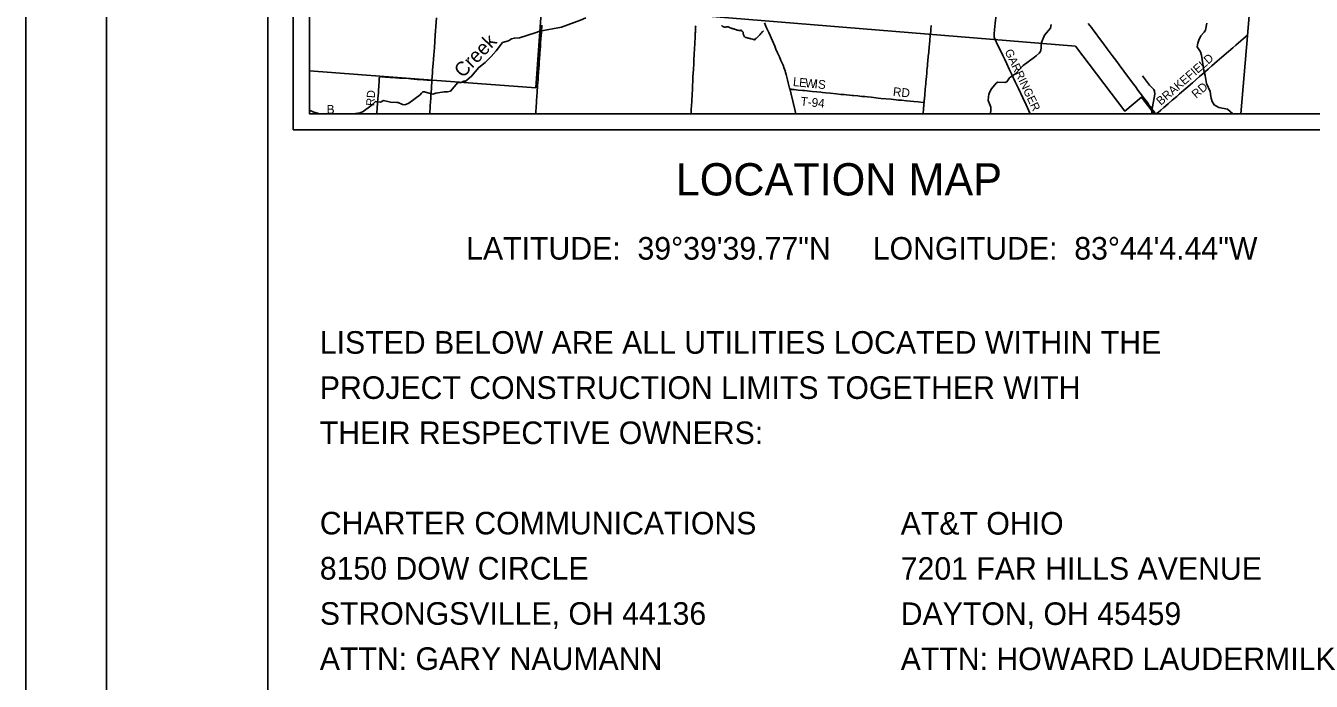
# Model space of a CAD drawing. Extents: x -13.9 to 69.1, y -25.2 to 26.1.
# Drawn here: x 0 to 7.96, y 10.9 to 14.96 of the extents above; entities that cross this region are included whole.
import ezdxf

# ---------------------------------------------------------------- set-up
doc = ezdxf.new("R2010")
doc.units = 0
for name, color, linetype in [('GM_X_County_Road', 7, 'Continuous'), ('GM_X_County_Road_Text', 7, 'Continuous'), ('GM_X_Minor_River', 7, 'Continuous'), ('GM_X_Minor_River_Text', 7, 'Continuous'), ('GM_X_State_Route', 7, 'Continuous'), ('GM_X_Township', 7, 'Continuous'), ('GM_X_Township_Road', 7, 'Continuous'), ('GM_X_Township_Road_Text', 7, 'Continuous'), ('SH_Border', 7, 'Continuous'), ('SH_Cut_Line', 7, 'Continuous'), ('SH_Data', 7, 'Continuous'), ('SH_Text', 7, 'Continuous')]:
    doc.layers.add(name, color=color, linetype=linetype)

msp = doc.modelspace()

# ---------------------------------------------------------------- linework, layer by layer
at = {"layer": 'GM_X_County_Road'}
for points in [[(5.9984, 14.8932), (5.9981, 14.8949), (5.9976, 14.8983), (5.9975, 14.9042), (5.9979, 14.9107), (6.0005, 14.9343), (6.0055, 14.9767), (6.0095, 15.0122), (6.0141, 15.0529), (6.0187, 15.0924), (6.0245, 15.1462), (6.03, 15.194), (6.0338, 15.224)], [(2.5162, 14.6214), (2.5164, 14.6263), (2.5173, 14.6411), (2.5177, 14.6476), (2.5179, 14.6506), (2.5187, 14.6636), (2.5195, 14.6754), (2.5204, 14.6879), (2.5234, 14.727), (2.5252, 14.7501), (2.5277, 14.7827), (2.529, 14.7987), (2.5312, 14.8272), (2.5338, 14.8597), (2.5371, 14.903), (2.5389, 14.9261), (2.5411, 14.9564), (2.5452, 15.0097)], [(6.5812, 14.9747), (6.6003, 14.9492), (6.6153, 14.9294), (6.6294, 14.9102), (6.6448, 14.8893), (6.6712, 14.854), (6.6979, 14.8177), (6.7298, 14.7751), (6.7573, 14.7385), (6.7733, 14.7173), (6.8023, 14.6783), (6.8244, 14.6485), (6.8327, 14.6374), (6.8617, 14.5984), (6.8735, 14.5826), (6.889, 14.5618), (6.9177, 14.5235)], [(3.1701, 14.5785), (3.1709, 14.5907), (3.1719, 14.6055), (3.1734, 14.6275), (3.1744, 14.6411), (3.177, 14.6761), (3.18, 14.7164), (3.1804, 14.7218), (3.1811, 14.733), (3.1847, 14.7846), (3.1849, 14.787), (3.1848, 14.7876), (3.1849, 14.7894), (3.1879, 14.8315), (3.1881, 14.8344), (3.1893, 14.851), (3.1915, 14.8836), (3.1924, 14.8979), (3.194, 14.9192), (3.1949, 14.9335), (3.1962, 14.9542), (3.1968, 14.9637)], [(4.1212, 14.4145), (4.1217, 14.4244), (4.1226, 14.4411), (4.1252, 14.491), (4.1279, 14.5384), (4.129, 14.5634), (4.1305, 14.5967), (4.1312, 14.6091), (4.133, 14.6436), (4.1354, 14.6887), (4.1373, 14.7255), (4.1385, 14.7486), (4.1391, 14.7599), (4.1399, 14.7736), (4.1406, 14.7866), (4.1423, 14.8151), (4.1428, 14.824), (4.1439, 14.8436), (4.1452, 14.8668), (4.1456, 14.8751), (4.1462, 14.8876), (4.1475, 14.9143), (4.1478, 14.9214), (4.1483, 14.9333), (4.1484, 14.9357), (4.1487, 14.9434), (4.1492, 14.9529), (4.1496, 14.9606)], [(6.2219, 14.4145), (6.1961, 14.47), (6.176, 14.5131), (6.1492, 14.5704), (6.1295, 14.6124), (6.1061, 14.6617), (6.0923, 14.6908), (6.0769, 14.7231), (6.064, 14.7501), (6.052, 14.7749), (6.029, 14.8236), (6.016, 14.8506), (6.0088, 14.866), (6.0037, 14.8771), (6.0015, 14.8823), (6.0003, 14.8856), (5.9993, 14.8888), (5.9986, 14.892), (5.9984, 14.8932)], [(2.5023, 14.4145), (2.5027, 14.4199), (2.5048, 14.4566), (2.5058, 14.4703), (2.5064, 14.4822), (2.5089, 14.5156), (2.5101, 14.5314), (2.5107, 14.5397), (2.5109, 14.5427), (2.5118, 14.5551), (2.5125, 14.5646), (2.5136, 14.5824), (2.5143, 14.5925), (2.515, 14.602), (2.5158, 14.6144), (2.5161, 14.6204), (2.5162, 14.6214)], [(3.1583, 14.4145), (3.1586, 14.4188), (3.1588, 14.4211), (3.1598, 14.4318), (3.1611, 14.449), (3.1617, 14.4579), (3.1635, 14.484), (3.1642, 14.4946), (3.1647, 14.5023), (3.1656, 14.5154), (3.1667, 14.5302), (3.1675, 14.5421), (3.1685, 14.5569), (3.1701, 14.5785)], [(6.9177, 14.5235), (6.9299, 14.5071), (6.9475, 14.4834), (6.9568, 14.4708), (6.9658, 14.4588), (6.9738, 14.4481), (6.9905, 14.4256)], [(6.9905, 14.4256), (6.9945, 14.4202), (6.9988, 14.4145)]]:
    msp.add_lwpolyline(points, dxfattribs=at)
at = {"layer": 'GM_X_Minor_River'}
for points in [[(3.1838, 14.9264), (3.3179, 14.9511), (3.4361, 14.9956), (3.4696, 15.0093)], [(7.3159, 14.9759), (7.3067, 14.932), (7.2998, 14.9201), (7.2789, 14.897), (7.2658, 14.8717), (7.2592, 14.8514), (7.2574, 14.8424), (7.2559, 14.8289), (7.2759, 14.7981), (7.2828, 14.7769), (7.2965, 14.6828), (7.3046, 14.6525), (7.3126, 14.6029), (7.3358, 14.5517), (7.3413, 14.5221), (7.3422, 14.5108), (7.3488, 14.4903), (7.3608, 14.4698), (7.3901, 14.4531), (7.4428, 14.4426), (7.461, 14.4278), (7.4758, 14.4145)], [(2.0173, 14.4145), (2.0292, 14.4149), (2.0714, 14.4212), (2.0904, 14.4282), (2.1377, 14.4642), (2.1479, 14.4724), (2.1667, 14.4907), (2.1973, 14.4867), (2.217, 14.4962), (2.2591, 14.4872), (2.2979, 14.4849), (2.3066, 14.4844), (2.3348, 14.4713), (2.3446, 14.4704), (2.3534, 14.4718), (2.3724, 14.4809), (2.4432, 14.5326), (2.451, 14.542), (2.4596, 14.5506), (2.4707, 14.5515), (2.4902, 14.5433), (2.5218, 14.5366), (2.5398, 14.5422), (2.5912, 14.5506), (2.6117, 14.5496), (2.6314, 14.5547), (2.6755, 14.6093), (2.6971, 14.6083), (2.7144, 14.6172), (2.7242, 14.6167), (2.733, 14.6224), (2.7613, 14.6467), (2.8064, 14.702), (2.8449, 14.7323), (2.8732, 14.7592), (2.8828, 14.7692), (2.9146, 14.8044), (2.9536, 14.8565), (2.9895, 14.8662), (3.0082, 14.879), (3.0268, 14.8835), (3.0579, 14.8849), (3.1554, 14.9155), (3.1838, 14.9264)], [(4.3097, 14.9615), (4.3113, 14.9604), (4.313, 14.9593), (4.3164, 14.9566), (4.3184, 14.9551), (4.3211, 14.954), (4.3231, 14.9532), (4.3255, 14.9528), (4.3282, 14.9517), (4.3312, 14.9516), (4.3332, 14.9516), (4.336, 14.9522), (4.3428, 14.9525), (4.3475, 14.9527), (4.3506, 14.9527), (4.3526, 14.9526), (4.3549, 14.9511), (4.3583, 14.95), (4.361, 14.9488), (4.3637, 14.9477), (4.3657, 14.9469), (4.3681, 14.9458), (4.3704, 14.9446), (4.3728, 14.9439), (4.3758, 14.9431), (4.3785, 14.9423), (4.3812, 14.9419), (4.3839, 14.9411), (4.3866, 14.9403), (4.3893, 14.9395), (4.3924, 14.9387), (4.3951, 14.9376), (4.3981, 14.9368), (4.4005, 14.9357), (4.4035, 14.9345), (4.4058, 14.9334), (4.4085, 14.9326), (4.4106, 14.9322), (4.4126, 14.9318), (4.4143, 14.9314), (4.417, 14.9313), (4.42, 14.9313), (4.4238, 14.9316), (4.4268, 14.9315), (4.4299, 14.9318), (4.4323, 14.9318), (4.4339, 14.9292), (4.4372, 14.9258), (4.4399, 14.924), (4.4416, 14.9221), (4.4429, 14.9203), (4.4436, 14.9177), (4.4445, 14.9155), (4.4448, 14.9137), (4.4448, 14.91), (4.4457, 14.906), (4.4467, 14.9038), (4.447, 14.9016), (4.448, 14.8994), (4.4486, 14.8972), (4.45, 14.8953), (4.4519, 14.892), (4.4539, 14.8905), (4.4556, 14.8894), (4.4586, 14.8875), (4.4627, 14.8863), (4.4684, 14.8844), (4.4742, 14.8828), (4.4799, 14.8824), (4.4843, 14.8819), (4.4877, 14.8808), (4.4904, 14.88), (4.4931, 14.8792), (4.5012, 14.8772), (4.5029, 14.8768), (4.5059, 14.876), (4.5079, 14.8749)], [(4.5079, 14.8749), (4.5096, 14.8738), (4.5116, 14.873), (4.5136, 14.8715), (4.5167, 14.8751), (4.5212, 14.8805), (4.5253, 14.8818), (4.5267, 14.884), (4.5295, 14.8872), (4.5316, 14.889), (4.5333, 14.8904), (4.5347, 14.8922), (4.5378, 14.8951), (4.5399, 14.8979), (4.5426, 14.9001), (4.5447, 14.9015), (4.5467, 14.904), (4.5495, 14.9072), (4.5512, 14.909), (4.5533, 14.9115), (4.5547, 14.9137), (4.5571, 14.9154), (4.5596, 14.9194), (4.5633, 14.923), (4.5664, 14.9247), (4.5678, 14.9273), (4.5688, 14.9272)], [(6.3524, 14.9678), (6.3465, 14.9446), (6.3108, 14.9021), (6.2921, 14.8561), (6.2891, 14.8336), (6.2904, 14.8215), (6.2851, 14.8012), (6.2779, 14.79), (6.2594, 14.7746), (6.2482, 14.7664), (6.1789, 14.7133), (6.1327, 14.664), (6.1139, 14.6508), (6.0925, 14.6369), (6.076, 14.6127), (6.0637, 14.6092), (6.0221, 14.6101), (6.0105, 14.6037), (5.981, 14.5691), (5.9686, 14.5467), (5.9648, 14.5344), (5.9626, 14.5206), (5.961, 14.4976), (5.9769, 14.4549), (5.978, 14.4334), (5.9733, 14.4145)], [(6.9757, 14.4145), (6.9756, 14.4349), (6.9939, 14.5351), (6.992, 14.5541), (6.9867, 14.5647), (6.9599, 14.5912), (6.9174, 14.6504)], [(1.7571, 14.4363), (1.7853, 14.4244), (1.8226, 14.4148), (1.8247, 14.4145)]]:
    msp.add_lwpolyline(points, dxfattribs=at)
at = {"layer": 'GM_X_State_Route'}
msp.add_lwpolyline([(4.7708, 14.4145), (4.7642, 14.4408), (4.7512, 14.4931), (4.7405, 14.5368), (4.734, 14.5621), (4.7331, 14.5656), (4.7289, 14.5821), (4.7228, 14.6062), (4.7179, 14.6252), (4.71, 14.6573), (4.7066, 14.6699), (4.7035, 14.6807), (4.6999, 14.6914), (4.6962, 14.7014), (4.6906, 14.715), (4.6778, 14.7447), (4.6682, 14.7668), (4.6573, 14.7921), (4.647, 14.8158), (4.6396, 14.8331), (4.6252, 14.8659), (4.602, 14.9179), (4.5889, 14.9481), (4.576, 14.9777)], dxfattribs=at)
at = {"layer": 'GM_X_Township'}
for points in [[(1.7571, 15.7823), (1.7571, 14.6812), (2.5192, 14.6233), (3.1591, 14.5746), (3.1593, 14.577), (3.1977, 15.0965)], [(4.1497, 15.026), (6.5016, 14.8337), (6.8084, 14.4299), (6.911, 14.518), (6.9888, 14.4145), (7.5262, 14.4145), (7.5668, 14.8972), (7.5796, 15.0495)]]:
    msp.add_lwpolyline(points, dxfattribs=at)
msp.add_lwpolyline([(1.7571, 14.6812), (1.7571, 14.4145), (6.9888, 14.4145), (6.911, 14.518), (6.8084, 14.4299), (6.5016, 14.8337), (4.1497, 15.026), (3.1986, 15.1105), (3.1977, 15.0965), (3.1593, 14.577), (3.1591, 14.5746), (2.5192, 14.6233)], close=True, dxfattribs=at)
at = {"layer": 'GM_X_Township_Road'}
for points in [[(5.5998, 14.8663), (5.6005, 14.8732), (5.6029, 14.8974), (5.604, 14.9105), (5.6044, 14.9152), (5.6054, 14.9252), (5.6056, 14.9272)], [(5.6056, 14.9272), (5.6064, 14.9359), (5.6071, 14.9436), (5.6081, 14.9554), (5.6087, 14.9625)], [(7.0037, 14.4145), (7.0045, 14.4152), (7.0137, 14.4228), (7.0306, 14.4373), (7.05, 14.454), (7.0764, 14.4766), (7.1009, 14.4979), (7.1292, 14.5226), (7.1459, 14.5373), (7.1856, 14.5715), (7.2261, 14.6065), (7.2704, 14.6459), (7.2924, 14.6649), (7.3234, 14.6917), (7.3463, 14.7114), (7.3791, 14.7396), (7.4093, 14.7656), (7.4494, 14.8003), (7.4762, 14.8232), (7.4952, 14.8395), (7.5262, 14.8664), (7.54, 14.8784), (7.5678, 14.9027)], [(5.5641, 14.4843), (5.5648, 14.4911), (5.5657, 14.5005), (5.566, 14.5047), (5.5666, 14.5118), (5.5683, 14.5307), (5.5717, 14.5674), (5.5747, 14.6), (5.5755, 14.6094), (5.5788, 14.6449), (5.5809, 14.6668), (5.5816, 14.6751), (5.5823, 14.6828), (5.5836, 14.6994), (5.5847, 14.7106), (5.5861, 14.7248), (5.5878, 14.7419), (5.5905, 14.7697), (5.592, 14.7839), (5.5929, 14.794), (5.5943, 14.8088), (5.5954, 14.8194), (5.5966, 14.8312), (5.5979, 14.8448), (5.5986, 14.8531), (5.5995, 14.8626), (5.5998, 14.8663)], [(2.1748, 14.4145), (2.1749, 14.4161), (2.1756, 14.4256), (2.1767, 14.4422), (2.1775, 14.4534), (2.1777, 14.457), (2.1787, 14.4718), (2.1798, 14.4872), (2.1811, 14.5026), (2.1819, 14.5121), (2.1829, 14.5245), (2.1845, 14.5487), (2.1853, 14.5605), (2.1867, 14.5836), (2.1872, 14.5925), (2.1884, 14.6132), (2.1893, 14.6269), (2.1896, 14.6317), (2.1902, 14.6363), (2.1904, 14.6374), (2.1911, 14.6392), (2.1919, 14.6406), (2.1934, 14.6423), (2.1947, 14.6433), (2.1956, 14.6438), (2.1958, 14.6439)], [(2.1958, 14.6439), (2.1967, 14.6443), (2.1977, 14.6446), (2.1989, 14.6448), (2.2011, 14.6448), (2.2033, 14.6447), (2.2082, 14.6442), (2.218, 14.6434), (2.2293, 14.6424), (2.2381, 14.6417), (2.2443, 14.6411), (2.2498, 14.6408), (2.2581, 14.6403), (2.2731, 14.6393), (2.2834, 14.6384), (2.2927, 14.6377), (2.3032, 14.6369), (2.3155, 14.6361), (2.3422, 14.6344), (2.371, 14.6322), (2.3848, 14.6313), (2.3985, 14.6301), (2.4068, 14.6293), (2.4162, 14.6286), (2.425, 14.6279), (2.4498, 14.626), (2.4647, 14.6248), (2.4773, 14.6239), (2.4873, 14.6232), (2.5093, 14.6219), (2.5104, 14.6218), (2.5162, 14.6214)], [(4.7331, 14.5656), (4.7351, 14.5658), (4.7369, 14.5661), (4.739, 14.5662), (4.7409, 14.5661), (4.7449, 14.5658), (4.7499, 14.5652), (4.7602, 14.5641), (4.7718, 14.5629), (4.7842, 14.5618), (4.8114, 14.5591), (4.824, 14.5578), (4.8702, 14.5532), (4.8994, 14.5503), (4.9242, 14.5479), (4.9357, 14.5468), (4.9561, 14.5447), (4.983, 14.5418), (5.0215, 14.5378), (5.049, 14.535), (5.0688, 14.533), (5.0842, 14.5315), (5.1024, 14.5297), (5.1194, 14.5281), (5.1266, 14.5274), (5.1541, 14.5248), (5.1783, 14.5225), (5.1976, 14.5206), (5.2147, 14.5189), (5.2361, 14.5166), (5.2652, 14.5134), (5.2801, 14.5119), (5.2971, 14.5101), (5.3599, 14.5042), (5.4067, 14.4998), (5.4237, 14.4981), (5.4562, 14.4951), (5.5018, 14.4903), (5.5277, 14.4878), (5.5585, 14.4848), (5.5641, 14.4843)], [(5.5589, 14.4145), (5.5592, 14.4201), (5.5596, 14.4266), (5.5601, 14.4349), (5.5611, 14.4509), (5.5614, 14.4557), (5.5618, 14.4598), (5.5625, 14.4673), (5.5629, 14.4716), (5.5641, 14.4834), (5.5641, 14.4843)]]:
    msp.add_lwpolyline(points, dxfattribs=at)
at = {"layer": 'SH_Border'}
for points in [[(0.5, 21.5), (1.5, 21.5), (1.5, 0.5), (0.5, 0.5)], [(1.5, 21.5), (33.5, 21.5), (33.5, 0.5), (1.5, 0.5)]]:
    msp.add_lwpolyline(points, close=True, dxfattribs=at)
at = {"layer": 'SH_Cut_Line'}
msp.add_lwpolyline([(0, 0), (34, 0), (34, 22), (0, 22)], close=True, dxfattribs=at)
at = {"layer": 'SH_Data'}
for p, q in [((1.6571, 21.3145), (1.6571, 14.3145)), ((1.7571, 21.2145), (1.7571, 14.4145)), ((1.7571, 14.4145), (8.5571, 14.4145)), ((1.6571, 14.3145), (8.6571, 14.3145))]:
    msp.add_line(p, q, dxfattribs=at)

# ---------------------------------------------------------------- texts
at = {"layer": 'GM_X_County_Road_Text'}
msp.add_text('GARRINGER', height=0.05135, rotation=295.3743, dxfattribs=at).set_placement((6.0621, 14.8009))
at = {"layer": 'GM_X_Minor_River_Text'}
msp.add_text('Creek', height=0.08758, rotation=46.10511, dxfattribs=at).set_placement((2.7072, 14.6324))
at = {"layer": 'GM_X_Township_Road_Text'}
for s, height, rotation, p in [('BRAKEFIELD', 0.05289, 41.02964, (7.0308, 14.4634)), ('L', 0.0544, 354.41535, (4.7503, 14.5868)), ('E', 0.0544, 354.41076, (4.788, 14.5831)), ('W', 0.0544, 354.41347, (4.8256, 14.5794)), ('I', 0.0544, 354.42442, (4.884, 14.5737)), ('S', 0.0544, 354.85229, (4.905, 14.5716)), ('RD', 0.05436, 354.70171, (5.3695, 14.5253)), ('RD', 0.05288, 41.10946, (7.2496, 14.5071)), ('RD', 0.05057, 85.87596, (2.1584, 14.4618)), ('T-94', 0.05435, 354.38102, (4.7974, 14.4659)), ('B', 0.0544, 1.8563, (1.865, 14.4145))]:
    msp.add_text(s, height=height, rotation=rotation, dxfattribs=at).set_placement(p)
at = {"layer": 'SH_Text'}
for s, height, p in [('LOCATION MAP', 0.2, (4.0262, 13.9082)), ('LATITUDE:  39°39\'39.77"N     LONGITUDE:  83°44\'4.44"W', 0.14, (2.7281, 13.5104)), ('LISTED BELOW ARE ALL UTILITIES LOCATED WITHIN THE ', 0.14, (1.8216, 12.927)), ('PROJECT CONSTRUCTION LIMITS TOGETHER WITH ', 0.14, (1.8216, 12.647)), ('THEIR RESPECTIVE OWNERS:', 0.14, (1.8216, 12.367)), ('CHARTER COMMUNICATIONS', 0.14, (1.8216, 11.807)), ('AT&T OHIO', 0.14, (5.4196, 11.8058)), ('8150 DOW CIRCLE', 0.14, (1.8216, 11.527)), ('7201 FAR HILLS AVENUE', 0.14, (5.4196, 11.5258)), ('STRONGSVILLE, OH 44136', 0.14, (1.8216, 11.247)), ('DAYTON, OH 45459', 0.14, (5.4196, 11.2458)), ('ATTN: GARY NAUMANN', 0.14, (1.8216, 10.967)), ('ATTN: HOWARD LAUDERMILK', 0.14, (5.4196, 10.9658))]:
    msp.add_text(s, height=height, dxfattribs=at).set_placement(p)

doc.saveas('drawing.dxf')
